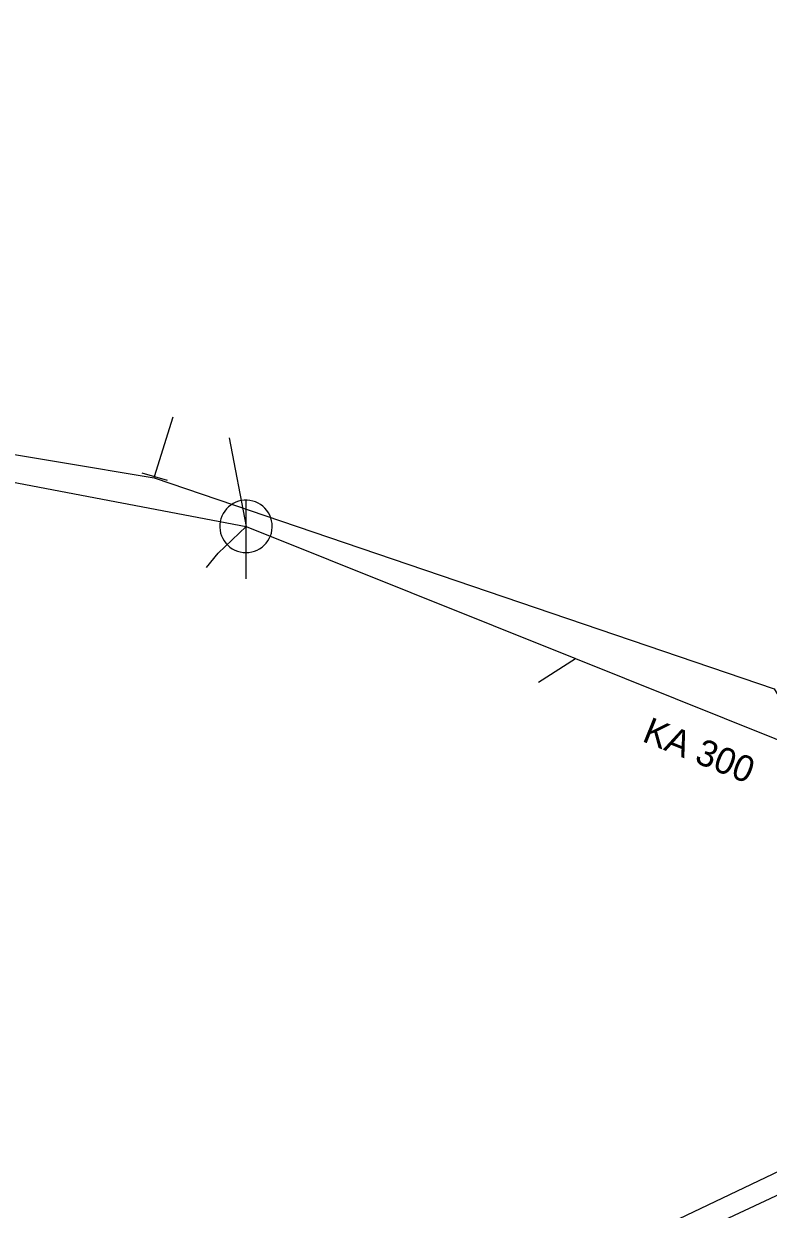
# Model space of a CAD drawing. Extents: x -690535 to -689974, y -975624 to -975325.
# Drawn here: x -690368.88 to -690340.48, y -975480.25 to -975435.01 of the extents above; entities that cross this region are included whole.
import ezdxf

# ---------------------------------------------------------------- set-up
doc = ezdxf.new("R2010")
doc.units = 0
doc.header["$LTSCALE"] = 0.4
for name, color, linetype, lineweight in [('1', 7, 'Continuous', 13), ('11', 7, 'Continuous', 13), ('13', 7, 'Continuous', 13), ('14', 7, 'Continuous', 25), ('17', 7, 'Continuous', 25), ('22', 7, 'Continuous', 13), ('34', 7, 'Continuous', 13)]:
    doc.layers.add(name, color=color, linetype=linetype, lineweight=lineweight)

msp = doc.modelspace()

# ---------------------------------------------------------------- linework, layer by layer
at = {"layer": '11'}
for p, q in [((-690361.041, -975450.807), (-690360.401, -975454.191)), ((-690349.239, -975460.136), (-690347.831, -975459.234))]:
    msp.add_line(p, q, dxfattribs=at)
msp.add_lwpolyline([(-690361.91, -975455.763), (-690361.458, -975455.212), (-690360.401, -975454.191)], dxfattribs=at)
at = {"layer": '13'}
msp.add_line((-690363.896, -975452.29), (-690363.177, -975450.011), dxfattribs=at)
at = {"layer": '14'}
for p, q in [((-690385.074, -975449.513), (-690360.401, -975454.191)), ((-690369.923, -975493.022), (-690316.232, -975467.417))]:
    msp.add_line(p, q, dxfattribs=at)
at = {"layer": '14', "lineweight": 13}
msp.add_line((-690363.91, -975452.34), (-690363.896, -975452.29), dxfattribs=at)
at = {"layer": '14'}
msp.add_lwpolyline([(-690360.401, -975454.191), (-690347.831, -975459.234), (-690323.219, -975469.109)], dxfattribs=at)
at = {"layer": '17'}
for points in [[(-690535.418, -975444.785), (-690534.453, -975442.263), (-690513.173, -975435.01), (-690489.543, -975438.213), (-690462.828, -975441.78), (-690461.125, -975442.127), (-690435.879, -975444.436), (-690407.486, -975446.66), (-690384.232, -975448.792), (-690371.219, -975451.123), (-690363.91, -975452.34), (-690340.249, -975460.384), (-690334.125, -975470.528)], [(-690487.124, -975551.552), (-690473.512, -975544.629), (-690473.092, -975544.418), (-690468.651, -975542.14), (-690430.232, -975523.675), (-690404.89, -975511.94), (-690401.289, -975510.34), (-690387.871, -975503.577), (-690350.486, -975484.551), (-690338.608, -975478.999)]]:
    msp.add_lwpolyline(points, dxfattribs=at)
at = {"layer": '22'}
msp.add_line((-690360.401, -975456.191), (-690360.4, -975453.191), dxfattribs=at)
msp.add_lwpolyline([(-690359.401, -975454.191), (-690359.406, -975454.082), (-690359.424, -975453.974), (-690359.454, -975453.868), (-690359.494, -975453.767), (-690359.546, -975453.67), (-690359.608, -975453.58), (-690359.68, -975453.497), (-690359.76, -975453.423), (-690359.848, -975453.357), (-690359.942, -975453.302), (-690360.042, -975453.257), (-690360.147, -975453.224), (-690360.254, -975453.202), (-690360.363, -975453.192), (-690360.473, -975453.194), (-690360.581, -975453.208), (-690360.688, -975453.233), (-690360.791, -975453.27), (-690360.889, -975453.319), (-690360.981, -975453.377), (-690361.067, -975453.446), (-690361.144, -975453.523), (-690361.213, -975453.609), (-690361.272, -975453.701), (-690361.32, -975453.799), (-690361.357, -975453.902), (-690361.383, -975454.009), (-690361.397, -975454.117), (-690361.4, -975454.227), (-690361.39, -975454.336), (-690361.369, -975454.443), (-690361.335, -975454.547), (-690361.291, -975454.647), (-690361.236, -975454.742), (-690361.17, -975454.83), (-690361.096, -975454.91), (-690361.013, -975454.982), (-690360.923, -975455.044), (-690360.827, -975455.096), (-690360.725, -975455.137), (-690360.62, -975455.167), (-690360.512, -975455.185), (-690360.402, -975455.191), (-690360.293, -975455.185), (-690360.185, -975455.167), (-690360.08, -975455.138), (-690359.978, -975455.097), (-690359.881, -975455.045), (-690359.791, -975454.983), (-690359.708, -975454.912), (-690359.633, -975454.832), (-690359.568, -975454.744), (-690359.512, -975454.65), (-690359.468, -975454.55), (-690359.434, -975454.446), (-690359.412, -975454.338), (-690359.402, -975454.229)], close=True, dxfattribs=at)
at = {"layer": '34'}
msp.add_line((-690364.377, -975452.153), (-690363.415, -975452.427), dxfattribs=at)

# ---------------------------------------------------------------- texts
at = {"layer": '1'}
msp.add_text('KA 300', height=1, rotation=338, dxfattribs=at).set_placement((-690345.334, -975462.374))

doc.saveas('drawing.dxf')
